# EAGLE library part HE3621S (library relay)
RELAY reed, 1 x norm. open with shield, grid 5.08 mm, Hamlin
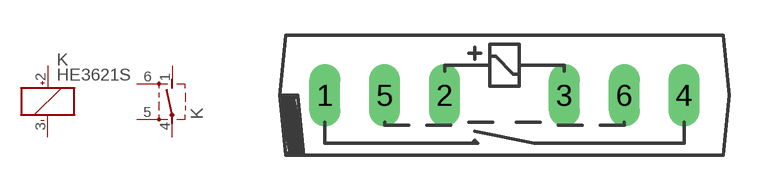
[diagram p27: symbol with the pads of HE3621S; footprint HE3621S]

Designator prefix K; gates 1=K+- 2=S_M2

## HE3621S (OC_FARNELL: unknown; OC_NEWARK: unknown)  [HE3621S]
1  2:S  pas
2  1:+  pas
3  1:-  pas
4  2:P  pas
5  2:ES  pas
6  2:ES  pas

## Footprint HE3621S (pad centres in mm)
RELAY reed, 1 x norm. open with shield, grid 5.08 mm, Hamlin
drill 0.813 long: 1 -7.62,0; 2 -2.54,0; 3 2.54,0; 4 7.62,0; 5 -5.08,0; 6 5.08,0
